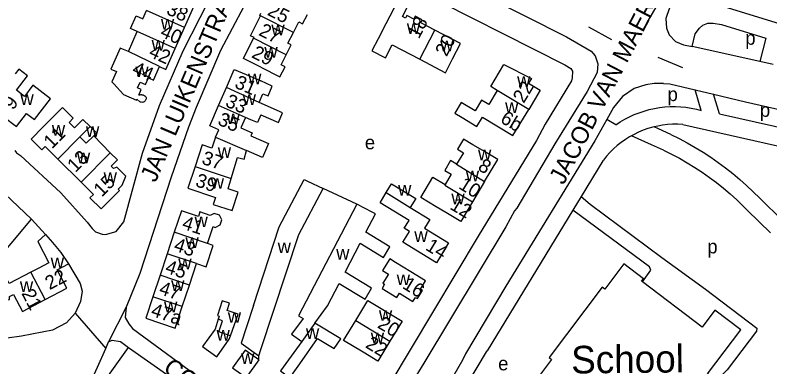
# Model space of a CAD drawing. Extents: x 159700 to 161346, y 381730 to 382922.
# Drawn here: x 160928.7 to 161147.7, y 382139.7 to 382241.7 of the extents above; entities that cross this region are included whole.
import ezdxf

# ---------------------------------------------------------------- set-up
doc = ezdxf.new("R2010")
doc.units = 0
for name, color, linetype in [('BLT_Basislijn', 7, 'Continuous'), ('BLT_Bebouwing', 7, 'Continuous'), ('BLT_Bebouwing_beschrifting', 7, 'Continuous'), ('BLT_Centroide', 7, 'Continuous'), ('BLT_Huisnummer', 7, 'Continuous'), ('BLT_Huisnummer_ tussenligend', 7, 'Continuous'), ('BLT_Onderverdeling_panden', 7, 'Continuous'), ('BLT_Straatnaam', 7, 'Continuous'), ('BLT_Vlakafsluiter', 7, 'Continuous')]:
    doc.layers.add(name, color=color, linetype=linetype)

msp = doc.modelspace()

# ---------------------------------------------------------------- linework, layer by layer
at = {"layer": 'BLT_Basislijn'}
for p, q in [((161115.43, 382245.43), (161111.99, 382239.54)), ((161095.06, 382238.31), (161101.69, 382234.63)), ((161146.45, 382235.02), (161144.74, 382228.2)), ((161144.74, 382228.2), (161125.14, 382232.59)), ((161115.18, 382229.47), (161122.3, 382226.53)), ((161148.65, 382227.32), (161144.74, 382228.2)), ((161126, 382219.97), (161131.29, 382218.72)), ((161127.75, 382214.05), (161126, 382219.97)), ((161133.09, 382213.02), (161131.29, 382218.72)), ((161102.95, 382209.85), (161100.35, 382211.36)), ((161122.38, 382209.98), (161221.8, 382187.57)), ((161115.4, 382208.65), (161114.06, 382209.25)), ((161118.98, 382207.03), (161115.4, 382208.65)), ((161113.35, 382204.09), (161107.56, 382206.69)), ((161116.85, 382202.51), (161113.35, 382204.09)), ((161099.21, 382199.44), (161092.93, 382189.07)), ((161027.81, 382186.87), (161018.12, 382191.39)), ((161092.93, 382189.07), (161090.53, 382185.11)), ((161144.83, 382188.45), (161151.35, 382182.11)), ((161090.53, 382185.11), (161065.68, 382144.3)), ((161141.19, 382185.02), (161147.87, 382178.52)), ((160960.95, 382156.98), (160955.84, 382146.97)), ((160951.4, 382131.05), (160961.58, 382145.32)), ((160999.42, 382141.73), (160999.4, 382142.85))]:
    msp.add_line(p, q, dxfattribs=at)
for points in [[(161157.33, 382307.36), (161155.87, 382308.04), (161153.79, 382308.04), (161152.42, 382307.37), (161151.3, 382306.22), (161146.63, 382297.57), (161141.2, 382286.87), (161140.09, 382285.05), (161118.46, 382243.46), (161117.44, 382240.72), (161117.66, 382237.93), (161118.49, 382235.91), (161120.31, 382234.05), (161122.64, 382233.1), (161125.14, 382232.59)], [(161008.63, 382269.77), (161010.76, 382271.59), (161013.31, 382272.48), (161015.18, 382272.35), (161017.01, 382271.87), (161019.15, 382270.98), (161028.46, 382266.01), (161028.46, 382265.85), (161088.67, 382235.33), (161095.8, 382231.18), (161096.96, 382229.85), (161097.74, 382227.52), (161097.61, 382225.06), (161094.68, 382219.53), (161085.25, 382204.39), (161074.24, 382185.72), (161073.56, 382184.87), (161071.06, 382180.3), (161047.27, 382140.74), (161036.56, 382123.35), (161029.07, 382112.84), (161025.18, 382106.67)], [(161008.63, 382269.77), (160988.34, 382231.44), (160981.25, 382214.87), (160978.99, 382209.19), (160973.96, 382194.72), (160964.93, 382166.74), (160960.95, 382156.98)], [(161215.7, 382219.01), (161214.79, 382219.29), (161134.08, 382244.18), (161130.58, 382245.86), (161129.71, 382246.65), (161128.76, 382248.88), (161128.82, 382251.75), (161138.45, 382270.09)], [(161024.3, 382261.18), (161043.39, 382250), (161088.17, 382227.24), (161089.95, 382226.24), (161090.37, 382225.38), (161090.36, 382223.49), (161090.08, 382222.64), (161082.45, 382210.07), (161079.93, 382205.32), (161063.02, 382177.55), (161030.66, 382123.41), (161020.13, 382109.52)], [(160828.73, 382252.07), (160829.72, 382251.88), (160832.18, 382250.64), (160855.26, 382237.21), (160858.7, 382235.39), (160869.71, 382228.86), (160872.45, 382227.61), (160873.32, 382226.88), (160874.69, 382222.21), (160875.39, 382221.63), (160892.46, 382211.94), (160900.47, 382207.13), (160901.54, 382206.71), (160904.95, 382206.79), (160905.68, 382206.37), (160913.45, 382200), (160918.08, 382196.48), (160919.9, 382194.81), (160921.88, 382193.4), (160933.46, 382182.5)], [(160928.68, 382202.38), (160929.12, 382201.78), (160930.24, 382200.99), (160941.98, 382190.14), (160949.64, 382181.6), (160951.03, 382179.78), (160952.08, 382178.81), (160953.97, 382178.17), (160954.95, 382178.09), (160958.08, 382178.95), (160960.26, 382181.74), (160965.67, 382201.68), (160970.65, 382215.49), (160977.5, 382231.28), (160987.29, 382250.72)], [(161125.14, 382232.59), (161125.95, 382236.22), (161127.21, 382237.91), (161128.18, 382238.78), (161129.62, 382239.32), (161131.23, 382239.36), (161133.64, 382239), (161146.45, 382235.02)], [(161116.81, 382221.8), (161114.11, 382221.84), (161111.68, 382221.46), (161108.25, 382220.44), (161104.9, 382218.04), (161102.35, 382214.86), (161100.35, 382211.36)], [(161116.81, 382221.8), (161118.65, 382221.7), (161126, 382219.97)], [(161131.29, 382218.72), (161140.61, 382216.52), (161221.78, 382198.08)], [(161102.95, 382209.85), (161104.23, 382210.69), (161105.55, 382211.47), (161106.91, 382212.18), (161108.31, 382212.81), (161109.73, 382213.38), (161111.19, 382213.86), (161112.67, 382214.27), (161114.16, 382214.61), (161115.68, 382214.86), (161117.2, 382215.03), (161118.73, 382215.13), (161120.26, 382215.15), (161121.79, 382215.08), (161123.32, 382214.94), (161124.84, 382214.71), (161126.34, 382214.41), (161127.75, 382214.05)], [(161133.09, 382213.02), (161217.57, 382194.12), (161219.96, 382194), (161221.08, 382194.77), (161221.59, 382196.07), (161221.78, 382198.08)], [(161100.35, 382211.36), (161096.84, 382205.22), (161071.04, 382163.1), (161059.39, 382143.45), (161058.53, 382141.6), (161051.65, 382129.76), (161044.99, 382118.92), (161032.54, 382101.14)], [(161122.38, 382209.98), (161120.92, 382210.04), (161119.46, 382210.03), (161118, 382209.93), (161116.55, 382209.75), (161115.12, 382209.5), (161114.06, 382209.25)], [(161114.06, 382209.25), (161113.7, 382209.17), (161112.3, 382208.76), (161110.92, 382208.27), (161109.57, 382207.71), (161108.26, 382207.07), (161107.56, 382206.69)], [(161107.56, 382206.69), (161106.98, 382206.37), (161105.74, 382205.59), (161104.55, 382204.75), (161103.41, 382203.85), (161102.31, 382202.88), (161101.27, 382201.86), (161100.29, 382200.78), (161099.37, 382199.64), (161099.21, 382199.44)], [(161118.98, 382207.03), (161121.37, 382205.86), (161123.71, 382204.62), (161126.02, 382203.3), (161128.29, 382201.92), (161130.52, 382200.47), (161132.7, 382198.96), (161134.83, 382197.38), (161136.92, 382195.73), (161138.95, 382194.02), (161140.93, 382192.26), (161142.86, 382190.43), (161144.73, 382188.55), (161144.83, 382188.45)], [(161116.85, 382202.51), (161119.16, 382201.37), (161121.44, 382200.16), (161123.68, 382198.88), (161125.88, 382197.53), (161128.03, 382196.12), (161130.14, 382194.63), (161132.21, 382193.09), (161134.22, 382191.48), (161136.18, 382189.8), (161138.09, 382188.07), (161139.95, 382186.28), (161141.19, 382185.02)], [(161092.93, 382189.07), (161095.55, 382186.88), (161116.32, 382171.39)], [(160862.63, 382185.55), (160872.52, 382180.8), (160905.59, 382169.8), (160907.5, 382169.24), (160918.66, 382169.32), (160920.93, 382168.39), (160921.57, 382168.42), (160933.46, 382182.5)], [(161110.74, 382164.31), (161113.14, 382167.69), (161112.71, 382168.63), (161090.53, 382185.11)], [(160933.46, 382182.5), (160937.58, 382178.06)], [(161116.32, 382171.39), (161129.01, 382162.24), (161143.87, 382150.87), (161143.81, 382150.02), (161135.23, 382138.79), (161132.2, 382135.72), (161129.56, 382137.63)], [(160944.21, 382169.54), (160947.63, 382163.8), (160948.19, 382161.66), (160947.69, 382158.66), (160946.11, 382155.27)], [(160946.11, 382155.27), (160943.66, 382152.45), (160939.58, 382150.34), (160930.62, 382148.56), (160926.43, 382147.98), (160915.76, 382147.11), (160901.7, 382146.68), (160874.21, 382146.92), (160855.55, 382147.72), (160852.49, 382146.89), (160850.46, 382145.69), (160848.98, 382144.21), (160846.78, 382140.3), (160846.37, 382140.25), (160845.56, 382140.51), (160836.96, 382145.22), (160828.6, 382150.66), (160826.49, 382151.73), (160810.64, 382161.06)], [(160960.95, 382156.98), (160960.62, 382153.99), (160961.67, 382152.16), (160962.77, 382150.82), (160987.65, 382132.51), (160989.89, 382131.71), (160992.43, 382132.1), (160994.34, 382133.92), (160995.72, 382136.55)], [(160955.05, 382145.03), (160955.84, 382146.97)], [(160955.84, 382146.97), (160956.87, 382147.4), (160959.25, 382147.01), (160961.58, 382145.32)], [(160944.71, 382121.92), (160949.88, 382133.55), (160952.62, 382139.62), (160955.05, 382145.03)], [(160961.58, 382145.32), (160979.13, 382132.96), (160982.29, 382130.32), (161007.11, 382112.95), (161017.79, 382105.04)], [(161044.2, 382109.19), (161050.77, 382118.9), (161053.72, 382124.45), (161065.49, 382144), (161065.68, 382144.3)]]:
    msp.add_lwpolyline(points, dxfattribs=at)
at = {"layer": 'BLT_Bebouwing'}
for p, q in [((160975.14, 382232), (160977.85, 382238.06)), ((160961.59, 382231.15), (160964.17, 382236.91)), ((161038.12, 382233.07), (161046.09, 382228.88)), ((160987.72, 382215.42), (160990.01, 382220.68)), ((160947.89, 382193.21), (160941.09, 382199.93)), ((161064.92, 382193.46), (161061.36, 382187.48)), ((160974.89, 382178.69), (160972.82, 382172.46)), ((160972.82, 382172.46), (160970.76, 382166.23)), ((160979.28, 382163.39), (160981.35, 382169.63)), ((160970.76, 382166.23), (160968.69, 382159.99)), ((160977.22, 382157.16), (160979.28, 382163.39)), ((160975.15, 382150.93), (160977.22, 382157.16)), ((161011.86, 382146.99), (161005.67, 382138.49)), ((160999.4, 382142.85), (161000, 382144.68)), ((160999.42, 382141.73), (160995.72, 382136.55))]:
    msp.add_line(p, q, dxfattribs=at)
for points in [[(160977.85, 382238.06), (160980.56, 382244.13), (160978.8, 382244.92)], [(161042.55, 382241.49), (161042.37, 382241.59), (161041.93, 382240.76), (161041.05, 382241.23), (161042.65, 382244.27), (161039.78, 382245.78), (161036.29, 382239.13), (161034.04, 382234.83), (161032.19, 382231.3), (161036.12, 382229.24), (161038.12, 382233.07)], [(160964.17, 382236.91), (160962.23, 382237.83), (160963.85, 382241.45), (160965.81, 382240.57), (160966.88, 382242.97)], [(160997.92, 382234.98), (160998.02, 382235.19), (160997.01, 382235.7), (160999.89, 382241.48)], [(160999.89, 382241.48), (160999.68, 382241.59), (161000, 382242.24)], [(161009.44, 382236.62), (161011, 382239.7), (161012.11, 382239.13), (161013.5, 382241.86)], [(161050.52, 382237.31), (161046.4, 382239.47), (161046.83, 382240.28), (161044.81, 382241.34), (161044.39, 382240.53), (161042.55, 382241.49)], [(161007.37, 382230.17), (161008.84, 382233.05), (161007.87, 382233.54), (161009.44, 382236.62)], [(161046.09, 382228.88), (161053.53, 382224.98), (161055.63, 382228.98), (161057.95, 382233.41), (161050.52, 382237.31)], [(161000.02, 382226.6), (160999.46, 382226.88), (160994.99, 382229.11), (160997.92, 382234.98)], [(160961.59, 382231.15), (160959.21, 382232.1), (160956.51, 382226.04), (160958.1, 382225.32), (160956.77, 382222.33), (160957.38, 382221.74), (160960.2, 382218.68), (160963.92, 382217.03), (160964.06, 382217.32), (160964.91, 382216.55)], [(160970.64, 382226.73), (160972.43, 382225.93), (160975.14, 382232)], [(161000.02, 382226.6), (161005.5, 382223.74), (161007.02, 382226.72), (161005.9, 382227.29), (161007.37, 382230.17)], [(161068.6, 382219.82), (161066.69, 382221.02), (161069.2, 382225.19), (161070.5, 382227.34), (161078.48, 382223.27), (161077.66, 382221.92), (161081.05, 382219.88), (161077.7, 382214.33)], [(160922.33, 382216.14), (160926.31, 382213.12), (160925.52, 382212.09), (160929.12, 382209.36), (160932.04, 382213.16), (160934.37, 382211.37), (160939.01, 382217.4), (160933.9, 382221.33), (160931.43, 382218.12), (160929.17, 382219.88), (160932.34, 382224.04), (160929.76, 382226), (160928.71, 382224.61)], [(160964.57, 382218.49), (160965.27, 382220.08), (160964.2, 382220.56), (160964.96, 382222.26), (160966.52, 382221.56), (160967.37, 382223.46), (160968.88, 382222.78), (160970.64, 382226.73)], [(160990.01, 382220.68), (160992.3, 382225.94), (160996.89, 382223.94), (161000.01, 382222.58)], [(160999.51, 382216.32), (161000.62, 382218.88), (161002.09, 382218.24), (161003.33, 382221.09), (161000.01, 382222.58)], [(160964.57, 382218.49), (160964.71, 382218.54), (160964.86, 382218.58), (160965.02, 382218.6), (160965.18, 382218.61), (160965.35, 382218.61), (160965.51, 382218.6), (160965.67, 382218.57), (160965.83, 382218.52), (160965.98, 382218.47), (160966.13, 382218.4), (160966.27, 382218.31), (160966.4, 382218.22), (160966.52, 382218.12), (160966.63, 382218.01)], [(161068.6, 382219.82), (161066.15, 382215.75), (161064.04, 382217.02), (161062.17, 382213.92), (161058.13, 382216.36), (161056.25, 382213.24), (161058.4, 382211.95), (161062.68, 382209.36), (161064.31, 382212.06), (161073.13, 382206.74), (161077.7, 382214.33)], [(160966.63, 382218.01), (160966.69, 382217.82), (160966.71, 382217.61), (160966.7, 382217.39), (160966.65, 382217.18), (160966.56, 382216.98), (160966.44, 382216.81), (160966.29, 382216.66), (160966.13, 382216.54), (160965.94, 382216.45), (160965.73, 382216.4), (160965.51, 382216.38), (160965.29, 382216.4), (160965.09, 382216.46), (160964.91, 382216.55)], [(161000, 382212.73), (161005.11, 382210.51), (161006.33, 382213.3), (160999.51, 382216.32)], [(160941.09, 382199.93), (160937.45, 382203.54), (160936.5, 382202.58), (160933.34, 382205.71), (160936.86, 382209.27), (160942.46, 382214.92)], [(160950.46, 382209.34), (160948.34, 382211.44), (160945.95, 382209.02), (160944.36, 382210.58), (160945.59, 382211.82), (160942.46, 382214.92)], [(160986.88, 382206.24), (160987.83, 382208.42), (160985.17, 382209.58), (160987.72, 382215.42)], [(160995.54, 382212.01), (160994.23, 382209), (160997.52, 382207.56), (160997.14, 382206.69), (161002.27, 382204.46), (161000.52, 382200.41), (160995.85, 382202.42)], [(161000, 382212.73), (160999.04, 382210.49), (160997.12, 382211.32), (160995.54, 382212.01)], [(160951.52, 382206.68), (160952.32, 382207.5), (160950.46, 382209.34)], [(160951.52, 382206.68), (160956.32, 382201.78)], [(160986.88, 382206.24), (160985.83, 382203.08), (160983.01, 382204.01), (160980.93, 382197.74)], [(161064.92, 382193.46), (161068.71, 382199.83), (161064.41, 382202.38), (161061.54, 382204.1), (161058.81, 382205.72), (161057.06, 382202.78), (161058.75, 382201.77), (161056.74, 382198.48)], [(160947.89, 382193.21), (160951.46, 382189.68), (160950.43, 382188.65), (160953.67, 382185.45), (160958.99, 382190.82), (160958.62, 382191.18), (160959.82, 382192.39), (160960.88, 382194.98), (160958.26, 382197.58), (160957.23, 382197.2), (160956.57, 382197.85), (160958.41, 382199.71), (160956.32, 382201.78)], [(160991.44, 382194.26), (160993.27, 382200.38), (160995.17, 382199.87), (160995.85, 382202.42)], [(161056.74, 382198.48), (161055.06, 382199.48), (161053.36, 382196.62), (161055.22, 382195.51), (161053.45, 382192.53)], [(160980.93, 382197.74), (160978.85, 382191.46), (160986.83, 382188.82), (160986.16, 382186.8), (160991.68, 382184.98), (160993.45, 382190.34), (160990.55, 382191.3), (160991.44, 382194.26)], [(161061.36, 382187.48), (161057.99, 382181.83), (161053.7, 382184.39), (161050.9, 382186.05), (161046.39, 382188.74), (161049.91, 382194.64), (161053.45, 382192.53)], [(160997.92, 382157.51), (161005.35, 382180.3), (161012.61, 382193.96), (161013.58, 382193.48), (161018.12, 382191.39)], [(161036.39, 382190.19), (161037.93, 382192.74), (161044.92, 382188.53), (161043.35, 382185.92)], [(161000, 382144.68), (161011.06, 382178.1), (161018.12, 382191.39)], [(161047.51, 382179.92), (161054.48, 382175.65), (161050.92, 382169.84), (161046.66, 382172.45), (161041.2, 382175.79), (161043.12, 382178.93), (161041.6, 382179.86), (161043.01, 382182.16), (161034.6, 382187.23), (161036.39, 382190.19)], [(161027.81, 382186.87), (161010.91, 382154.43), (161012.28, 382153.72), (161008.93, 382149.12), (161011.86, 382146.99)], [(161015.71, 382152.35), (161019.36, 382157.36), (161022.71, 382163.81), (161030.24, 382159.33), (161032.14, 382162.52), (161024.43, 382167.11), (161028.83, 382175.54), (161035.59, 382171.43), (161037.44, 382174.49), (161030.48, 382178.71), (161033.25, 382184.04), (161032.25, 382184.56), (161027.81, 382186.87)], [(161043.35, 382185.92), (161049.05, 382182.43), (161047.51, 382179.92)], [(160984.56, 382175.48), (160986.17, 382180.34), (160986.79, 382180.13), (160988.18, 382180.83), (160988.67, 382182.31), (160987.97, 382183.7), (160986.49, 382184.19), (160985.31, 382183.6), (160982.35, 382184.58), (160981.92, 382183.27), (160976.96, 382184.92), (160974.89, 382178.69)], [(160937.58, 382178.06), (160935.33, 382176.02), (160938.54, 382169.81), (160935.45, 382168.22), (160933.31, 382167.12)], [(160937.58, 382178.06), (160939.6, 382175.76), (160941.95, 382172.85), (160944.21, 382169.54)], [(160981.35, 382169.63), (160984.14, 382168.66), (160986.18, 382174.82), (160984.56, 382175.48)], [(161040.2, 382161.04), (161044.14, 382158.62), (161044.87, 382159.82), (161045.47, 382159.45), (161046.93, 382161.84), (161046.34, 382162.21), (161047.8, 382164.59), (161043.54, 382167.21), (161039.09, 382169.93), (161037.39, 382170.98), (161035.29, 382167.57), (161037, 382166.52), (161035.43, 382163.97), (161035.92, 382163.67), (161035.16, 382162.44), (161039.44, 382159.81), (161040.2, 382161.04)], [(160937.41, 382159.17), (160943.7, 382162.5), (160940.96, 382167.81), (160944.21, 382169.54)], [(161110.97, 382165.24), (161105.32, 382169.52), (161099.8, 382162.2), (161099.04, 382162.77), (161083.61, 382142.34), (161084.35, 382141.78), (161078.82, 382134.46)], [(160933.31, 382167.12), (160927.03, 382163.87), (160925.87, 382166.12), (160924.01, 382165.16)], [(161110.74, 382164.31), (161110.43, 382164.54), (161110.97, 382165.24)], [(161129.56, 382137.63), (161139.21, 382150.44), (161131.71, 382156.07), (161128.05, 382151.19), (161110.74, 382164.31)], [(160923.96, 382161.18), (160924.03, 382159.12), (160927.12, 382159.23), (160927.09, 382160.09), (160928.29, 382160.7), (160930.86, 382155.71), (160937.41, 382159.17)], [(160968.69, 382159.99), (160966.62, 382153.76), (160975.15, 382150.93)], [(160991.19, 382148.7), (160993.42, 382154.96), (160990.23, 382156.01), (160990.93, 382158.15), (160988.8, 382158.85), (160987.39, 382154.58), (160987.96, 382154.39), (160987.65, 382153.47)], [(160997.92, 382157.51), (160995.84, 382151.26), (160994.27, 382146.52), (160999.4, 382142.85)], [(161027.51, 382153.11), (161031.03, 382158.95), (161040.95, 382152.95), (161037.45, 382147.13)], [(160987.65, 382153.47), (160986.71, 382150.63), (160983.08, 382145.55), (160987.2, 382142.6)], [(161037.45, 382147.13), (161033.95, 382141.32), (161029.66, 382143.9), (161024.02, 382147.3), (161027.51, 382153.11)], [(161005.67, 382138.49), (161008.39, 382136.51), (161011.33, 382140.55), (161016.47, 382147.89), (161021.28, 382144.97), (161023.19, 382147.81), (161015.71, 382152.35)], [(160987.2, 382142.6), (160990.83, 382147.69), (160991.19, 382148.7)], [(160999.42, 382141.73), (160995.5, 382144.52), (160991.8, 382139.35), (160995.72, 382136.55)]]:
    msp.add_lwpolyline(points, dxfattribs=at)
at = {"layer": 'BLT_Onderverdeling_panden'}
for p, q in [((160977.85, 382238.06), (160966.88, 382242.97)), ((161009.44, 382236.62), (160999.89, 382241.48)), ((160975.14, 382232), (160964.17, 382236.91)), ((161046.09, 382228.88), (161050.52, 382237.31)), ((161007.37, 382230.17), (160997.92, 382234.98)), ((160970.64, 382226.73), (160961.59, 382231.15)), ((160999.51, 382216.32), (160990.01, 382220.68)), ((161077.7, 382214.33), (161068.6, 382219.82)), ((160995.54, 382212.01), (160987.72, 382215.42)), ((160947.49, 382206.34), (160950.46, 382209.34)), ((160941.09, 382199.93), (160947.49, 382206.34)), ((160986.88, 382206.24), (160995.85, 382202.42)), ((160947.89, 382193.21), (160956.32, 382201.78)), ((160980.93, 382197.74), (160991.44, 382194.26)), ((161056.74, 382198.48), (161064.92, 382193.46)), ((161036.39, 382190.19), (161043.35, 382185.92)), ((160984.56, 382175.48), (160974.89, 382178.69)), ((160981.35, 382169.63), (160972.82, 382172.46)), ((160937.41, 382159.17), (160933.31, 382167.12)), ((160979.28, 382163.39), (160970.76, 382166.23)), ((160977.22, 382157.16), (160968.69, 382159.99)), ((161027.51, 382153.11), (161037.45, 382147.13)), ((161015.71, 382152.35), (161011.86, 382146.99))]:
    msp.add_line(p, q, dxfattribs=at)
for points in [[(160951.52, 382206.68), (160949.36, 382204.5), (160947.49, 382206.34)], [(161053.45, 382192.53), (161053.35, 382192.37), (161061.36, 382187.48)], [(160991.19, 382148.7), (160987.81, 382149.82), (160988.88, 382153.05), (160987.65, 382153.47)], [(160991.2, 382148.7), (160991.09, 382148.74)]]:
    msp.add_lwpolyline(points, dxfattribs=at)
at = {"layer": 'BLT_Vlakafsluiter'}
msp.add_line((160946.11, 382155.27), (160955.05, 382145.03), dxfattribs=at)

# ---------------------------------------------------------------- texts
at = {"layer": 'BLT_Bebouwing_beschrifting'}
msp.add_text('School', height=8, rotation=0.5918, dxfattribs=at).set_placement((161090.06, 382137.73))
at = {"layer": 'BLT_Centroide'}
for s, p in [('w', (160971.01, 382237.5)), ('w', (161003.05, 382235.81)), ('w', (161042.35, 382236.22)), ('p', (161140.53, 382233.08)), ('w', (160968.3, 382231.41)), ('w', (161052.02, 382231.16)), ('w', (161001.03, 382229.34)), ('w', (160963.58, 382223.69)), ('w', (160996.3, 382221.59)), ('w', (161074.34, 382220.84)), ('w', (160930.25, 382215.59)), ('w', (160994.71, 382215.59)), ('p', (161117.99, 382216.75)), ('w', (161070.86, 382213.28)), ('p', (161144.77, 382212.17)), ('w', (160990.05, 382210.06)), ('w', (160939.38, 382206.72)), ('w', (160949.28, 382206.32)), ('e', (161030.18, 382202.76)), ('w', (160987.5, 382200.25)), ('w', (160946.64, 382198.72)), ('w', (161062.99, 382199.59)), ('w', (161059.45, 382193.47)), ('w', (160954.39, 382192.98)), ('w', (160985.46, 382191.31)), ('w', (161039.81, 382189.34)), ('w', (161055.27, 382186.84)), ('w', (160980.76, 382180.19)), ('w', (161044.53, 382175.86)), ('w', (160978.12, 382174.16)), ('w', (161004.87, 382172.66)), ('p', (161129.52, 382172.58)), ('w', (161021.85, 382170.77)), ('w', (160939.05, 382168.23)), ('w', (160976.05, 382167.94)), ('w', (161039.41, 382163.37)), ('w', (160930.1, 382161.41)), ('w', (160973.98, 382161.69)), ('w', (160971.92, 382155.47)), ('w', (160990.41, 382152.45)), ('w', (161034.25, 382153.03)), ('w', (161013.09, 382147.77)), ('w', (160987.14, 382147.28)), ('w', (161031.9, 382146.5)), ('w', (160994.28, 382140.53)), ('e', (161068.84, 382138.66))]:
    msp.add_text(s, height=4, dxfattribs=at).set_placement(p)
at = {"layer": 'BLT_Huisnummer'}
for s, rotation, p in [('18', 62.3043, (161045.83, 382234.58)), ('40', 335.9146, (160970.54, 382235.55)), ('27', 333.029, (160999.13, 382235.98)), ('20', 62.3064, (161053.88, 382229.43)), ('29', 333.4554, (160997.05, 382229.51)), ('44', 335.9195, (160962.34, 382224.8)), ('31', 336.4498, (160992.12, 382220.77)), ('22', 58.91, (161076.26, 382215.9)), ('9', 52.7612, (160928.09, 382213.93)), ('35', 336.4389, (160987.23, 382210.04)), ('6b', 328.9075, (161069.19, 382210.75)), ('11', 45.0862, (160939.39, 382202.7)), ('37', 341.678, (160982.59, 382198.63)), ('8', 328.4742, (161062.69, 382196.96)), ('15', 45.2894, (160953.89, 382188.76)), ('39', 341.6837, (160980.76, 382192.13)), ('12', 329.2204, (161054.58, 382185.6)), ('41', 341.6356, (160976.88, 382179.81)), ('14', 328.5351, (161047.5, 382173.78)), ('22', 27.2916, (160938.72, 382161.9)), ('47', 341.6336, (160970.21, 382160.86)), ('16', 328.4888, (161040.82, 382162.64)), ('21', 297.293, (160930.48, 382161.01)), ('47a', 341.6353, (160967.86, 382154.52)), ('20', 328.9598, (161033.58, 382151.2)), ('22', 328.9616, (161030.09, 382145.43))]:
    msp.add_text(s, height=4, rotation=rotation, dxfattribs=at).set_placement(p)
at = {"layer": 'BLT_Huisnummer_ tussenligend'}
for s, rotation, p in [('38', 335.9149, (160972.33, 382242.08)), ('25', 333.019, (161001.65, 382241.85)), ('42', 335.9146, (160967.22, 382229.76)), ('33', 336.4498, (160989.43, 382215.34)), ('13', 45.0863, (160946.22, 382195.84)), ('10', 328.4742, (161057.13, 382191.57)), ('43', 341.6356, (160974.52, 382173.47)), ('45', 341.6336, (160972.02, 382167.05))]:
    msp.add_text(s, height=4, rotation=rotation, dxfattribs=at).set_placement(p)
at = {"layer": 'BLT_Straatnaam'}
for s, rotation, p in [('JACOB VAN MAERLANTLAAN', 62.5214, (161087.82, 382192.23)), ('JAN LUIKENSTRAAT', 66.8483, (160969.47, 382192.92)), ('COUPERUSPAD', 324.6541, (160971.38, 382138.52))]:
    msp.add_text(s, height=5, rotation=rotation, dxfattribs=at).set_placement(p)

doc.saveas('drawing.dxf')
